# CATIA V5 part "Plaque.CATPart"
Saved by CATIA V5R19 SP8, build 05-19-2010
Part number: Plaque
Nomenclature: 89
Bounding box of the stored display mesh (mm): x -293 to 293, y 411.923 to 1556.923, z 0 to 18
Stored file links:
  C:\Users\rphgr\Desktop\0_Tapis_TC520B_vitesse\Plaque.CATPart
  D:\Documents\1_Travail\1 - ac-limoges.fr\ac-limoges.fr\Emmanuel Maynard - STI2D_Turgot\3 - Supports\Tapis de course TC520B\Tapis de course TC520B_Ca\0_Tapis_TC520B.CATProduct
  C:\Users\rphgr\Desktop\0_Tapis_TC520B_vitesse\Silembloc.CATPart
  D:\Documents\1_Travail\1 - ac-limoges.fr\ac-limoges.fr\Emmanuel Maynard - STI2D_Turgot\3 - Supports\Tapis de course TC520B\Tapis de course TC520B_Ca\Cadre Plateau.CATPart
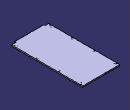
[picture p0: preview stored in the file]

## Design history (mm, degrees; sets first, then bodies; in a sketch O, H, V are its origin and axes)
AxisSystem1: origin (0, 0, 0), X (1, 0, 0), Y (0, 1, 0), Z (0, 0, 1)
Set1
  DatumCurve1 to DatumCurve4: linked copy from another document
Body1 (main body)
  Sketch1 on xy-plane, origin (0, 0, 0), H (1, 0, 0), V (0, 1, 0)
    point P1 (0, 984.4226)
    line L1 (293, 1556.9226) -> (293, 431.9226)
    line L2 (223, 411.9226) -> (-237, 411.9226)
    line L3 (-293, 431.9226) -> (-293, 1556.9226)
    line L4 (-293, 1556.9226) -> (293, 1556.9226)
    line L5 (-293, 431.9226) -> (-237, 431.9226)
    line L6 (-237, 431.9226) -> (-237, 411.9226)
    line L7 (223, 411.9226) -> (223, 431.9226)
    line L8 (223, 431.9226) -> (293, 431.9226)
    distance L3 L1 = 586
    distance L4 L2 = 1145
    distance L7 L1 = 70
    distance L6 L3 = 56
    distance L2 L5 = 20
    coincidence: P1 V, L5 L8
    vertical: L1 V, L3 V, L6 V, L7 V
    horizontal: L2 H, L4 H, L5 H, L8 H
    equidistance: L1 L3 P1, L2 L4 P1
  Pad1: profile Sketch1, direction (0, 0, 1), length 18
  Sketch2 on end face of Pad1, origin (225.3714, 470.0336, 18), H (1, 0, 0), V (0, 1, 0)
    point P1 (53.6286, -3.611)
    reference projected point E1 (53.6286, -3.611) from edge of DatumCurve1
    coincidence: P1 E1
  Hole1: placed by Sketch2, at (279, 466.4226, 18) direction (0, 0, -1), diameter 6.4, through (limit type 3), type CounterDrilledType, Diameter 6.4, Sketch Sketch2, Profile a sketch, ThreadDepth 10, DiameterThread 11, Pas 1, Diameter 9.5, Angle 90, Depth 2.54
  Sketch3 on end face of Pad1, origin (268.5143, 815.5463, 18), H (1, 0, 0), V (0, 1, 0)
    point P1 (10.4857, -1.6237)
    reference projected point E1 (10.4857, -1.6237) from edge of DatumCurve2
    coincidence: P1 E1
  Hole2: placed by Sketch3, at (279, 813.9226, 18) direction (0, 0, -1), diameter 6.4, through (limit type 3), type CounterDrilledType, Diameter 6.4, Sketch Sketch3, Profile a sketch, ThreadDepth 10, DiameterThread 7.04, Pas 1, Diameter 9.5, Angle 90, Depth 2.54
  Sketch4 on end face of Pad1, origin (282.7065, 1172.8638, 18), H (1, 0, 0), V (0, 1, 0)
    point P1 (-3.7065, -3.9412)
    reference projected point E1 (-3.7065, -3.9412) from edge of DatumCurve3
    coincidence: P1 E1
  Hole3: placed by Sketch4, at (279, 1168.9226, 18) direction (0, 0, -1), diameter 6.4, through (limit type 3), type CounterDrilledType, Diameter 6.4, Sketch Sketch4, Profile a sketch, ThreadDepth 10, DiameterThread 7.04, Pas 1, Diameter 9.5, Angle 90, Depth 2.54
  Sketch5 on end face of Pad1, origin (268.3927, 1518.7855, 18), H (1, 0, 0), V (0, 1, 0)
    point P1 (9.6073, 0.1371)
    reference projected point E1 (9.6073, 0.1371) from edge of DatumCurve4
    coincidence: P1 E1
  Hole4: placed by Sketch5, at (278, 1518.9226, 18) direction (0, 0, -1), diameter 6.4, through (limit type 3), type CounterDrilledType, Diameter 6.4, Sketch Sketch5, Profile a sketch, ThreadDepth 10, DiameterThread 7.04, Pas 1, Diameter 9.5, Angle 90, Depth 2.54
  Mirror1: of Hole1, Hole2, Hole3, Hole4, about yz-plane
  Sketch6 on end face of Pad1, origin (-230.141, 537.4645, 18), H (1, 0, 0), V (0, 1, 0)
    point P1 (-32.859, -40.5419)
    reference intersected line E1 (-62.859, -105.5419) -> (-62.859, 1019.4581) from face of Pad1 from Sketch1.L3
    reference intersected line E2 (-6.859, -105.5419) -> (-62.859, -105.5419) from face of Pad1 from Sketch1.L5
    distance P1 E1 = 30
    distance P1 E2 = 65
  Hole5: placed by Sketch6, at (-263, 496.9226, 18) direction (0, 0, -1), diameter 3, depth 15
  RectPattern1: of Hole5, direction 1 instances 4, spacing 335, along edge [face of Pad1 from Sketch1.L3 | end face of Pad1] reversed, direction 2 instances 2, spacing 522, along edge [face of Pad1 from Sketch1.L2 | end face of Pad1]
